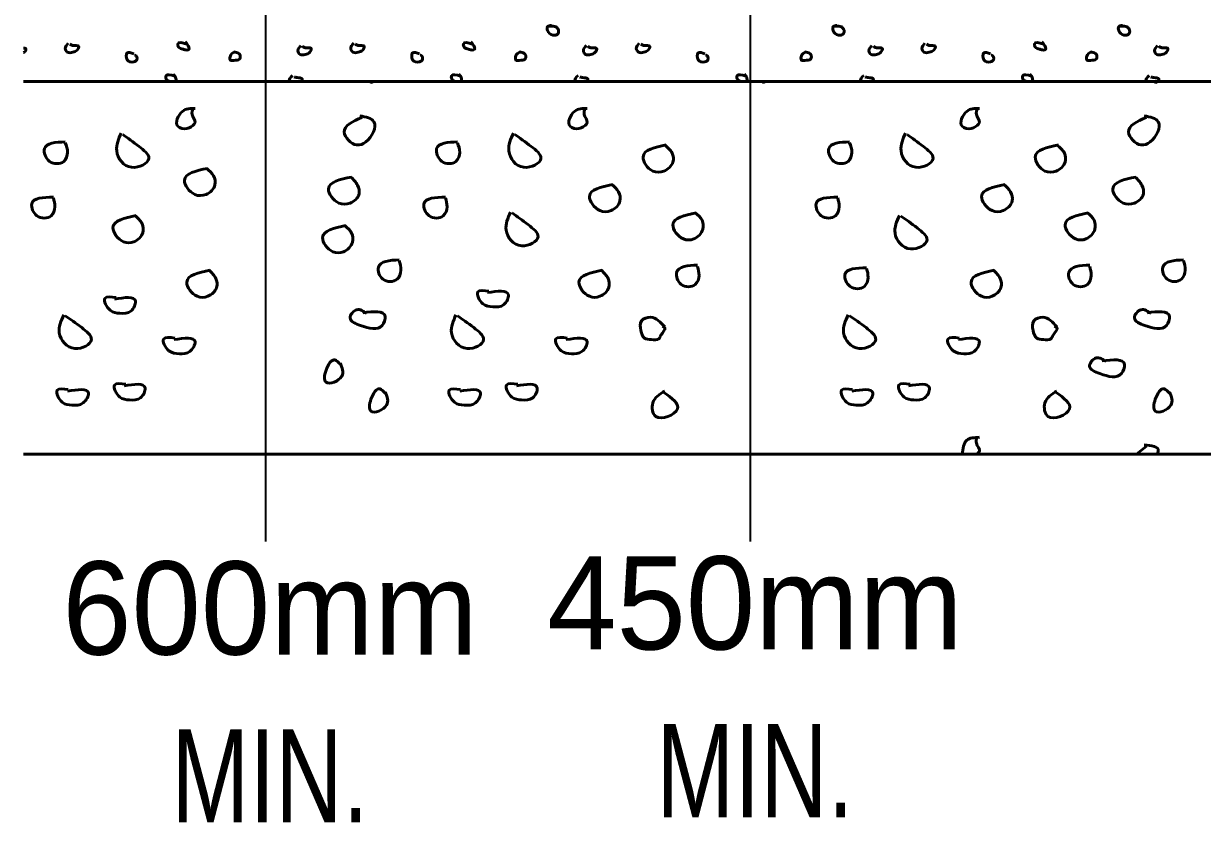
# Model space of a CAD drawing. Extents: x -50 to 806, y -9 to 535.
# Drawn here: x 393.58 to 431.53, y 174.38 to 200.09 of the extents above; entities that cross this region are included whole.
import ezdxf
from ezdxf.enums import TextEntityAlignment as Align

# ---------------------------------------------------------------- set-up
doc = ezdxf.new("R2010")
doc.units = 0
doc.header["$LTSCALE"] = 1.2
doc.layers.add('1', color=7, linetype='Continuous', lineweight=35)

msp = doc.modelspace()

# ---------------------------------------------------------------- linework, layer by layer
at = {"layer": '1'}
for p, q in [((401.381, 183.423), (401.381, 225.827)), ((416.981, 183.423), (416.981, 210.227))]:
    msp.add_line(p, q, dxfattribs=at)
at = {"layer": '1', "lineweight": 53}
for p, q in [((393.581, 198.227), (508.781, 198.227)), ((429.724, 186.487), (429.412, 186.227)), ((508.781, 186.227), (393.581, 186.227))]:
    msp.add_line(p, q, dxfattribs=at)
for points in [[(410.57, 200.03), (410.45, 199.982), (410.45, 199.862), (410.618, 199.718), (410.786, 199.766), (410.786, 199.91), (410.714, 199.982), (410.546, 200.006), (410.474, 200.006)], [(419.762, 200.03), (419.642, 199.982), (419.642, 199.862), (419.81, 199.718), (419.978, 199.766), (419.978, 199.91), (419.906, 199.982), (419.738, 200.006), (419.666, 200.006)], [(428.954, 200.03), (428.834, 199.982), (428.834, 199.862), (429.002, 199.718), (429.17, 199.766), (429.17, 199.91), (429.098, 199.982), (428.93, 200.006), (428.858, 200.006)], [(393.581, 199.156), (393.602, 199.166), (393.65, 199.286), (393.581, 199.295)], [(395.018, 199.454), (394.922, 199.286), (394.994, 199.166), (395.162, 199.166), (395.306, 199.238), (395.354, 199.358), (395.162, 199.382), (395.066, 199.43)], [(398.834, 199.43), (398.546, 199.43), (398.57, 199.334), (398.714, 199.262), (398.834, 199.238), (398.906, 199.262), (398.858, 199.406), (398.786, 199.502)], [(402.506, 199.382), (402.41, 199.214), (402.482, 199.094), (402.65, 199.094), (402.794, 199.166), (402.842, 199.286), (402.65, 199.31), (402.554, 199.358)], [(404.21, 199.454), (404.114, 199.286), (404.186, 199.166), (404.354, 199.166), (404.498, 199.238), (404.546, 199.358), (404.354, 199.382), (404.258, 199.43)], [(408.026, 199.43), (407.738, 199.43), (407.762, 199.334), (407.906, 199.262), (408.026, 199.238), (408.098, 199.262), (408.05, 199.406), (407.978, 199.502)], [(411.698, 199.382), (411.602, 199.214), (411.674, 199.094), (411.842, 199.094), (411.986, 199.166), (412.034, 199.286), (411.842, 199.31), (411.746, 199.358)], [(413.402, 199.454), (413.306, 199.286), (413.378, 199.166), (413.546, 199.166), (413.69, 199.238), (413.738, 199.358), (413.546, 199.382), (413.45, 199.43)], [(420.89, 199.382), (420.794, 199.214), (420.866, 199.094), (421.034, 199.094), (421.178, 199.166), (421.226, 199.286), (421.034, 199.31), (420.938, 199.358)], [(422.594, 199.454), (422.498, 199.286), (422.57, 199.166), (422.738, 199.166), (422.882, 199.238), (422.93, 199.358), (422.738, 199.382), (422.642, 199.43)], [(426.41, 199.43), (426.122, 199.43), (426.146, 199.334), (426.29, 199.262), (426.41, 199.238), (426.482, 199.262), (426.434, 199.406), (426.362, 199.502)], [(430.082, 199.382), (429.986, 199.214), (430.058, 199.094), (430.226, 199.094), (430.37, 199.166), (430.418, 199.286), (430.226, 199.31), (430.13, 199.358)], [(397.13, 199.118), (396.914, 199.142), (396.914, 198.926), (397.13, 198.854), (397.226, 198.926), (397.178, 199.07), (397.154, 199.07)], [(400.394, 199.19), (400.226, 199.022), (400.25, 198.902), (400.346, 198.902), (400.538, 198.95), (400.538, 199.094), (400.394, 199.166), (400.346, 199.166)], [(406.322, 199.118), (406.106, 199.142), (406.106, 198.926), (406.322, 198.854), (406.418, 198.926), (406.37, 199.07), (406.346, 199.07)], [(409.586, 199.19), (409.418, 199.022), (409.442, 198.902), (409.538, 198.902), (409.73, 198.95), (409.73, 199.094), (409.586, 199.166), (409.538, 199.166)], [(415.514, 199.118), (415.298, 199.142), (415.298, 198.926), (415.514, 198.854), (415.61, 198.926), (415.562, 199.07), (415.538, 199.07)], [(418.778, 199.19), (418.61, 199.022), (418.634, 198.902), (418.73, 198.902), (418.922, 198.95), (418.922, 199.094), (418.778, 199.166), (418.73, 199.166)], [(424.706, 199.118), (424.49, 199.142), (424.49, 198.926), (424.706, 198.854), (424.802, 198.926), (424.754, 199.07), (424.73, 199.07)], [(427.97, 199.19), (427.802, 199.022), (427.826, 198.902), (427.922, 198.902), (428.114, 198.95), (428.114, 199.094), (427.97, 199.166), (427.922, 199.166)], [(398.45, 198.398), (398.162, 198.398), (398.186, 198.278), (398.288, 198.227)], [(398.494, 198.227), (398.474, 198.35), (398.402, 198.47)], [(407.642, 198.398), (407.354, 198.398), (407.378, 198.278), (407.48, 198.227)], [(407.686, 198.227), (407.666, 198.35), (407.594, 198.47)], [(416.834, 198.398), (416.546, 198.398), (416.57, 198.278), (416.672, 198.227)], [(416.878, 198.227), (416.858, 198.35), (416.786, 198.47)], [(426.026, 198.398), (425.738, 198.398), (425.762, 198.278), (425.864, 198.227)], [(426.07, 198.227), (426.05, 198.35), (425.978, 198.47)], [(402.242, 198.422), (402.146, 198.23), (402.148, 198.227)], [(402.535, 198.227), (402.554, 198.302), (402.386, 198.35), (402.29, 198.374)], [(404.838, 198.227), (404.764, 198.199), (404.764, 198.227)], [(411.434, 198.422), (411.338, 198.23), (411.34, 198.227)], [(411.727, 198.227), (411.746, 198.302), (411.578, 198.35), (411.482, 198.374)], [(417.462, 198.227), (417.388, 198.199), (417.388, 198.227)], [(420.626, 198.422), (420.53, 198.23), (420.532, 198.227)], [(420.919, 198.227), (420.938, 198.302), (420.77, 198.35), (420.674, 198.374)], [(429.818, 198.422), (429.722, 198.23), (429.724, 198.227)], [(430.111, 198.227), (430.13, 198.302), (429.962, 198.35), (429.866, 198.374)], [(430.086, 198.227), (430.012, 198.199), (430.012, 198.227)], [(399.1, 197.359), (398.692, 197.263), (398.548, 196.783), (398.836, 196.711), (398.908, 196.735), (399.1, 196.903), (399.004, 197.167), (399.028, 197.359)], [(411.724, 197.359), (411.316, 197.263), (411.172, 196.783), (411.46, 196.711), (411.532, 196.735), (411.724, 196.903), (411.628, 197.167), (411.652, 197.359)], [(424.348, 197.359), (423.94, 197.263), (423.796, 196.783), (424.084, 196.711), (424.156, 196.735), (424.348, 196.903), (424.252, 197.167), (424.276, 197.359)], [(404.476, 197.071), (403.9, 196.591), (404.308, 196.183), (404.596, 196.279), (404.86, 196.927), (404.404, 197.119)], [(429.724, 197.071), (429.148, 196.591), (429.556, 196.183), (429.844, 196.279), (430.108, 196.927), (429.652, 197.119)], [(394.924, 196.279), (394.252, 196.063), (394.42, 195.655), (394.876, 195.655), (394.996, 195.943), (394.924, 196.255)], [(396.724, 196.567), (396.58, 195.991), (397.06, 195.463), (397.612, 195.751), (397.3, 196.135), (396.772, 196.519)], [(407.548, 196.279), (406.876, 196.063), (407.044, 195.655), (407.5, 195.655), (407.62, 195.943), (407.548, 196.255)], [(409.348, 196.567), (409.204, 195.991), (409.684, 195.463), (410.236, 195.751), (409.924, 196.135), (409.396, 196.519)], [(420.172, 196.279), (419.5, 196.063), (419.668, 195.655), (420.124, 195.655), (420.244, 195.943), (420.172, 196.255)], [(421.972, 196.567), (421.828, 195.991), (422.308, 195.463), (422.86, 195.751), (422.548, 196.135), (422.02, 196.519)], [(414.268, 196.183), (413.524, 195.799), (413.836, 195.343), (414.196, 195.343), (414.484, 195.631), (414.46, 195.919), (414.22, 196.183)], [(426.892, 196.183), (426.148, 195.799), (426.46, 195.343), (426.82, 195.343), (427.108, 195.631), (427.084, 195.919), (426.844, 196.183)], [(399.502, 195.429), (398.758, 195.045), (399.094, 194.589), (399.454, 194.589), (399.742, 194.901), (399.694, 195.189), (399.478, 195.429)], [(404.14, 195.151), (403.396, 194.767), (403.732, 194.311), (404.092, 194.311), (404.38, 194.599), (404.332, 194.887), (404.116, 195.151)], [(429.388, 195.151), (428.644, 194.767), (428.98, 194.311), (429.34, 194.311), (429.628, 194.599), (429.58, 194.887), (429.364, 195.151)], [(412.54, 194.911), (411.796, 194.527), (412.132, 194.071), (412.492, 194.071), (412.78, 194.383), (412.732, 194.671), (412.516, 194.911)], [(425.164, 194.911), (424.42, 194.527), (424.756, 194.071), (425.116, 194.071), (425.404, 194.383), (425.356, 194.671), (425.14, 194.911)], [(394.54, 194.503), (393.844, 194.287), (394.012, 193.903), (394.468, 193.903), (394.588, 194.191), (394.54, 194.479)], [(407.164, 194.503), (406.468, 194.287), (406.636, 193.903), (407.092, 193.903), (407.212, 194.191), (407.164, 194.479)], [(419.788, 194.503), (419.092, 194.287), (419.26, 193.903), (419.716, 193.903), (419.836, 194.191), (419.788, 194.479)], [(409.256, 194.019), (409.112, 193.443), (409.616, 192.939), (410.144, 193.227), (409.832, 193.611), (409.304, 193.995)], [(415.228, 193.999), (414.484, 193.615), (414.82, 193.159), (415.156, 193.159), (415.444, 193.471), (415.42, 193.759), (415.204, 193.999)], [(421.777, 193.916), (421.633, 193.34), (422.137, 192.836), (422.665, 193.124), (422.353, 193.508), (421.825, 193.892)], [(427.852, 193.999), (427.108, 193.615), (427.444, 193.159), (427.78, 193.159), (428.068, 193.471), (428.044, 193.759), (427.828, 193.999)], [(397.203, 193.909), (396.459, 193.525), (396.795, 193.069), (397.131, 193.069), (397.419, 193.357), (397.395, 193.645), (397.179, 193.909)], [(403.949, 193.585), (403.205, 193.201), (403.541, 192.745), (403.877, 192.745), (404.165, 193.057), (404.141, 193.345), (403.925, 193.585)], [(405.676, 192.487), (405.004, 192.247), (405.148, 191.863), (405.604, 191.863), (405.724, 192.151), (405.676, 192.463)], [(430.924, 192.487), (430.252, 192.247), (430.396, 191.863), (430.852, 191.863), (430.972, 192.151), (430.924, 192.463)], [(399.58, 192.151), (398.836, 191.767), (399.172, 191.311), (399.508, 191.311), (399.796, 191.599), (399.772, 191.887), (399.556, 192.151)], [(412.204, 192.151), (411.46, 191.767), (411.796, 191.311), (412.132, 191.311), (412.42, 191.599), (412.396, 191.887), (412.18, 192.151)], [(415.276, 192.319), (414.604, 192.079), (414.748, 191.695), (415.204, 191.695), (415.324, 191.983), (415.276, 192.271)], [(420.718, 192.229), (420.022, 192.013), (420.19, 191.629), (420.646, 191.629), (420.766, 191.917), (420.718, 192.205)], [(424.828, 192.151), (424.084, 191.767), (424.42, 191.311), (424.756, 191.311), (425.044, 191.599), (425.02, 191.887), (424.804, 192.151)], [(427.9, 192.319), (427.228, 192.079), (427.372, 191.695), (427.828, 191.695), (427.948, 191.983), (427.9, 192.271)], [(396.51, 191.222), (397.182, 191.15), (397.038, 190.838), (396.678, 190.766), (396.366, 190.862), (396.198, 191.246), (396.558, 191.27)], [(408.514, 191.429), (409.186, 191.357), (409.042, 191.045), (408.682, 190.973), (408.37, 191.069), (408.202, 191.453), (408.562, 191.477)], [(404.5, 190.783), (405.22, 190.663), (405.124, 190.375), (404.428, 190.375), (404.092, 190.615), (404.308, 190.879), (404.62, 190.759)], [(429.748, 190.783), (430.468, 190.663), (430.372, 190.375), (429.676, 190.375), (429.34, 190.615), (429.556, 190.879), (429.868, 190.759)], [(394.876, 190.711), (394.732, 190.135), (395.236, 189.631), (395.764, 189.919), (395.452, 190.303), (394.924, 190.687)], [(407.5, 190.711), (407.356, 190.135), (407.86, 189.631), (408.388, 189.919), (408.076, 190.303), (407.548, 190.687)], [(414.22, 190.327), (413.764, 190.639), (413.476, 190.519), (413.452, 190.207), (413.572, 189.967), (413.788, 189.919), (414.028, 189.943), (414.1, 190.063), (414.22, 190.303), (414.148, 190.351)], [(420.124, 190.711), (419.98, 190.135), (420.484, 189.631), (421.012, 189.919), (420.7, 190.303), (420.172, 190.687)], [(426.844, 190.327), (426.388, 190.639), (426.1, 190.519), (426.076, 190.207), (426.196, 189.967), (426.412, 189.919), (426.652, 189.943), (426.724, 190.063), (426.844, 190.303), (426.772, 190.351)], [(398.428, 189.919), (399.1, 189.847), (398.932, 189.535), (398.596, 189.463), (398.26, 189.559), (398.092, 189.943), (398.452, 189.967)], [(411.052, 189.919), (411.724, 189.847), (411.556, 189.535), (411.22, 189.463), (410.884, 189.559), (410.716, 189.943), (411.076, 189.967)], [(423.676, 189.919), (424.348, 189.847), (424.18, 189.535), (423.844, 189.463), (423.508, 189.559), (423.34, 189.943), (423.7, 189.967)], [(403.773, 189.169), (403.821, 188.738), (403.317, 188.546), (403.317, 188.93), (403.605, 189.266), (403.773, 189.121)], [(428.301, 189.233), (429.021, 189.113), (428.925, 188.825), (428.229, 188.825), (427.893, 189.065), (428.109, 189.329), (428.421, 189.209)], [(394.996, 188.263), (395.668, 188.191), (395.5, 187.879), (395.14, 187.807), (394.828, 187.903), (394.66, 188.287), (395.02, 188.311)], [(396.82, 188.431), (397.492, 188.359), (397.348, 188.047), (396.988, 187.975), (396.676, 188.071), (396.508, 188.455), (396.868, 188.479)], [(405.22, 188.239), (405.268, 187.807), (404.764, 187.615), (404.764, 187.999), (405.052, 188.335), (405.22, 188.191)], [(407.62, 188.263), (408.292, 188.191), (408.124, 187.879), (407.764, 187.807), (407.452, 187.903), (407.284, 188.287), (407.644, 188.311)], [(409.444, 188.431), (410.116, 188.359), (409.972, 188.047), (409.612, 187.975), (409.3, 188.071), (409.132, 188.455), (409.492, 188.479)], [(414.196, 188.215), (414.628, 187.687), (413.932, 187.447), (413.836, 187.879), (414.22, 188.263)], [(420.244, 188.263), (420.916, 188.191), (420.748, 187.879), (420.388, 187.807), (420.076, 187.903), (419.908, 188.287), (420.268, 188.311)], [(422.068, 188.431), (422.74, 188.359), (422.596, 188.047), (422.236, 187.975), (421.924, 188.071), (421.756, 188.455), (422.116, 188.479)], [(426.82, 188.215), (427.252, 187.687), (426.556, 187.447), (426.46, 187.879), (426.844, 188.263)], [(430.468, 188.239), (430.516, 187.807), (430.012, 187.615), (430.012, 187.999), (430.3, 188.335), (430.468, 188.191)], [(424.348, 186.775), (423.94, 186.679), (423.804, 186.227)], [(424.243, 186.227), (424.348, 186.319), (424.252, 186.583), (424.276, 186.775)], [(430.061, 186.227), (430.108, 186.343), (429.652, 186.535)]]:
    msp.add_spline(points, degree=3, dxfattribs=at)

# ---------------------------------------------------------------- texts
at = {"layer": '1'}
for s, p in [('450mm', (417.127, 179.946)), ('600mm', (401.515, 179.781))]:
    msp.add_text(s, height=3, dxfattribs=at).set_placement(p, align=Align.CENTER)
at = {"layer": '1', "width": 0.75}
for p in [(401.515, 174.381), (417.127, 174.546)]:
    msp.add_text('MIN.', height=3, dxfattribs=at).set_placement(p, align=Align.CENTER)

doc.saveas('drawing.dxf')
